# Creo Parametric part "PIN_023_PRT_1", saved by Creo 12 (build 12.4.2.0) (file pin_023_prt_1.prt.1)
Units: Custom; MM, KILOGRAM, SECS

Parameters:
  PTC_WM_ITERATION = "0"
  PTC_WM_VERSION = "-.0"
  PTC_WM_LIFECYCLE_STATE = "In Work"
  PTC_WM_LIFECYCLE = "MO_CADDocument"
  PTC_WM_CREATED_BY = "Maximilian Roepper (Z0017RMS: MO)"
  PTC_WM_CREATED_ON = "18-Sep-26 11:36:42 AM"
  PTC_WM_MODIFIED_BY = "Maximilian Roepper (Z0017RMS: MO)"
  PTC_WM_MODIFIED_ON = "18-Sep-26 11:36:46 AM"
  PDMLINKNUMBER = "PDM000071455319"
  PTC_WM_NAME = "pin_023_prt_1.prt"
  PTC_WM_NUMBER = "PDM000071455319"

Other parameters: WEIGHT, WEIGHT_FACTOR, WEIGHT_ADD, _MASS_TEMP, _DIFF_TEMP, MC_ERRORS, SUPPLIER

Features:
  1. coordinate system
  2. datum plane "PRT_YZ"
  3. datum plane "PRT_XY"
  4. datum plane "PRT_XZ"
  5. coordinate system
  6. datum axis
  7. datum axis
  8. datum axis
  9. coordinate system
  10. imported feature
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
Other named items: PRT, SIEMENS_MO, DRW_VIEW_ORG, PRT_X, PRT_Y, PRT_Z, CS0, ROUGH_GROB

Layers: 00_STD_CSYS-KSYS, 01_STD_PLANES-EBENEN, 02_STD_AXES-ACHSEN, 03_STD_CSYS-KSYS, 24_IMPORT_FEAT-IMPORT_KE

Surfaces: 9 plane, 1 cylinder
